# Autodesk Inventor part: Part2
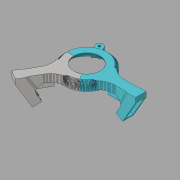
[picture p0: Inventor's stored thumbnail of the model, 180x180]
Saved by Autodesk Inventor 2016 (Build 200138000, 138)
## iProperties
Created: 2016-03
Part Number: Part2
Material: Generic
Document SubType Name: Modeling
Designer: bongo_000
Density: 1 g/cm^3
Appearance: Default
Author: bongo_000
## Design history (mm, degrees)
feature "Part2"
node "Repaired Geometry1"
  feature "Base2" [MeshFeature]
feature "MeshFeature1"
sketch "Sketch1"
  geometry: L1 (-59.882, 11.054)-(-59.328, 12.087) reference; L2 (-59.328, 12.087)-(-58.71, 13.083) reference; L3 (-58.71, 13.083)-(-58.03, 14.038) reference; L4 (-58.03, 14.038)-(-57.291, 14.948) reference; L5 (-57.291, 14.948)-(-56.496, 15.809) reference; L6 (-56.496, 15.809)-(-55.647, 16.618) reference; L7 (-55.647, 16.618)-(-54.749, 17.372) reference; L8 (-54.749, 17.372)-(-53.805, 18.067) reference; L9 (-53.805, 18.067)-(-52.819, 18.7) reference; L10 (-52.819, 18.7)-(-51.795, 19.27) reference; L11 (-51.795, 19.27)-(-50.736, 19.774) reference; L12 (-50.736, 19.774)-(-49.648, 20.21) reference; L13 (-49.648, 20.21)-(-48.534, 20.576) reference; L14 (-48.534, 20.576)-(-47.399, 20.87) reference; L15 (-47.399, 20.87)-(-46.248, 21.092) reference; L16 (-46.248, 21.092)-(-45.085, 21.24) reference; L17 (-45.085, 21.24)-(-43.915, 21.315) reference; L18 (-43.915, 21.315)-(-42.743, 21.315) reference; L19 (-42.743, 21.315)-(-41.573, 21.24) reference; L20 (-41.573, 21.24)-(-40.41, 21.092) reference; L21 (-40.41, 21.092)-(-39.259, 20.87) reference; L22 (-39.259, 20.87)-(-38.125, 20.576) reference; L23 (-38.125, 20.576)-(-37.011, 20.21) reference; L24 (-37.011, 20.21)-(-35.922, 19.774) reference; L25 (-35.922, 19.774)-(-34.864, 19.27) reference; L26 (-34.864, 19.27)-(-33.84, 18.7) reference; L27 (-33.84, 18.7)-(-32.853, 18.067) reference; L28 (-32.853, 18.067)-(-31.909, 17.372) reference; L29 (-31.909, 17.372)-(-31.011, 16.618) reference; L30 (-31.011, 16.618)-(-30.163, 15.809) reference; L31 (-30.163, 15.809)-(-29.367, 14.948) reference; L32 (-29.367, 14.948)-(-28.628, 14.038) reference; L33 (-28.628, 14.038)-(-27.948, 13.083) reference; L34 (-27.948, 13.083)-(-27.33, 12.087) reference; L35 (-27.33, 12.087)-(-26.777, 11.054) reference; L36 (-26.777, 11.054)-(-26.29, 9.987) reference; L37 (-26.29, 9.987)-(-25.871, 8.892) reference; L38 (-25.871, 8.892)-(-25.523, 7.773) reference; L39 (-25.523, 7.773)-(-25.247, 6.634) reference; L40 (-25.247, 6.634)-(-25.043, 5.479) reference; L41 (-25.043, 5.479)-(-24.913, 4.314) reference; L42 (-24.913, 4.314)-(-24.858, 3.143) reference; L43 (-24.876, 1.971)-(-24.858, 3.143) reference; L44 (-24.969, 0.802)-(-24.876, 1.971) reference; L45 (-25.136, -0.358)-(-24.969, 0.802) reference; L46 (-25.376, -1.505)-(-25.136, -0.358) reference; L47 (-25.688, -2.635)-(-25.376, -1.505) reference; L48 (-26.072, -3.743)-(-25.688, -2.635) reference; L49 (-26.525, -4.824)-(-26.072, -3.743) reference; L50 (-27.045, -5.875)-(-26.525, -4.824) reference; L51 (-27.631, -6.89)-(-27.045, -5.875) reference; L52 (-28.281, -7.866)-(-27.631, -6.89) reference; L53 (-28.991, -8.799)-(-28.281, -7.866) reference; L54 (-29.758, -9.685)-(-28.991, -8.799) reference; L55 (-30.581, -10.52)-(-29.758, -9.685) reference; L56 (-31.454, -11.302)-(-30.581, -10.52) reference; L57 (-32.376, -12.027)-(-31.454, -11.302) reference; L58 (-33.341, -12.691)-(-32.376, -12.027) reference; L59 (-34.347, -13.294)-(-33.341, -12.691) reference; L60 (-35.389, -13.831)-(-34.347, -13.294) reference; L61 (-36.463, -14.301)-(-35.389, -13.831) reference; L62 (-37.565, -14.702)-(-36.463, -14.301) reference; L63 (-38.69, -15.032)-(-37.565, -14.702) reference; L64 (-39.833, -15.29)-(-38.69, -15.032) reference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; A1 r 18.474 centre (-43.329, 2.85) between (-26.29, 9.987) and (-24.858, 3.143); A2 r 100 centre (-43.329, 2.85) between (6.671, 89.453) and (6.671, -83.753); 1 further point
  constraints: 6 end point, 6 point on circle, 2 centre point, 1 horizontal
  dimensions: "d0" = 120 deg angle of L238 L237; "d1" = 120 deg angle of L238 L239 (= d0); "d2" = 200 diameter of A2
extrude "Extrusion1" cut sketch "Sketch1" stored distance "d3" = 0; taper "d4" = 0 deg
workplane "Work Plane1"
split "Split1"
  body "Solid1"
sketch "Sketch2"
  geometry: L1 (0, 0)-(100, 0) reference; L2 (0, 0)-(0, -50); 1 further point
  constraints: 2 end point, 1 vertical
  dimensions: "d6" = 50 distance of L1.start L2.end
workaxis "Work Axis1"
feature "Move Body1"
combine "Combine1"
  body "Solid2"
node "Projected Loop1"
body "Solid3"
body "Solid4"
other parameters: "d5" = 90 deg, "d7" = 120 deg
